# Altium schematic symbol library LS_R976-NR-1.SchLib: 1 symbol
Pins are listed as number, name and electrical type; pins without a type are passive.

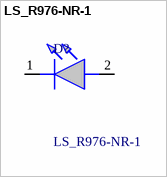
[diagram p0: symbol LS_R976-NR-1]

## LS_R976-NR-1
designator D?
Standard LEDs - SMD Super Red, 633nm 180mcd, 20mA; Manufacturer_Name: OSRAM; Manufacturer_Part_Number: LS R976-NR-1; Geometry.Height: 0.4mm
footprint LEDC2012X40N
pins: 1 K, 2 A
